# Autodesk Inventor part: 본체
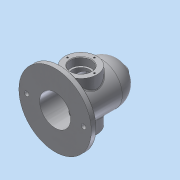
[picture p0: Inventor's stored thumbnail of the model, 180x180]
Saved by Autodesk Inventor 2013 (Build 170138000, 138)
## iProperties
Created: 2019-11
Part Number: 본체
Material: 알루미늄 6061
Document SubType Name: Modeling
Designer: Administrator
Density: 2.71 g/cm^3
Mass: 1114.82 g
Surface Area: 885.864 cm^2
Volume: 411.372 cm^3
Author: Administrator
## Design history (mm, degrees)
sketch "스케치1"
  geometry: C1 r 31 at (0, 0); 1 further point
  constraints: 1 centre point, 1 coincident
  dimensions: "d3" = 62 diameter of C1
extrude "돌출1" new body sketch "스케치1" stored distance "d4" = 100; taper "d5" = 0 deg
node "작업 평면1"
sketch "스케치2"
  geometry: C1 r 70 at (0, 0); 1 further point
  constraints: 1 centre point, 1 coincident
  dimensions: "d7" = 140 diameter of C1
extrude "돌출2" join sketch "스케치2" distance "d8" = 10; taper "d9" = 0 deg
sketch "스케치3"
  geometry: C1 r 70 at (0, 0) reference; C2 r 40 at (0, 0)
  constraints: 1 centre point, 1 coincident
  dimensions: "d10" = 80 diameter of C2
extrude "돌출3" join sketch "스케치3" distance "d11" = 80; taper "d12" = 0 deg
sketch "스케치5"
  geometry: L1 (31, -50)-(-31, -50) reference; L2 (-31, -50)-(-31, -40) reference; L3 (-40, 70)-(-40, 40) reference; L4 (-50, 70)-(-40, 70) reference; L5 (-50, -70)-(-50, 70) reference; L6 (-40, -70)-(-50, -70) reference; L7 (-40, -40)-(-40, -70) reference; L8 (-31, 40)-(-31, 50) reference; L9 (-31, 50)-(31, 50) reference; L10 (31, 50)-(31, 40) reference; L11 (31, 40)-(40, 40) reference; L12 (40, 40)-(40, -40) reference; L13 (40, -40)-(31, -40) reference; L14 (31, -40)-(31, -50) reference; L15 (-40, 40)-(-31, 40) reference; L16 (-31, -40)-(-40, -40) reference; A1 r 40 centre (40, 0) between (40, -40) and (40, 40); 1 further point
  constraints: 2 end point, 2 point on circle, 1 centre point, 1 midpoint
revolve "회전1" sketch "스케치5" stored, may be unused: angle "d13" = 90 deg
sketch "스케치6"
  geometry: C1 r 31 at (0, 0) reference; C2 r 20 at (0, 0)
  constraints: 1 centre point, 1 coincident
  dimensions: "d14" = 40 diameter of C2
extrude "돌출4" cut sketch "스케치6" distance "d15" = 15; taper "d16" = 0 deg
sketch "스케치7"
  geometry: C1 r 20 at (0, 0) reference; C2 r 16.5 at (0, 0)
  constraints: 1 centre point, 1 coincident
  dimensions: "d17" = 33 diameter of C2
extrude "돌출5" cut sketch "스케치7" stored distance "d18" = 15; taper "d19" = 0 deg
sketch "스케치8" dims "d20" = 52
  geometry: C1 r 20 at (0, 0) reference; C2 r 31 at (0, 0) reference; 2 further points
  constraints: 2 vertical alignment, 1 coincident, 2 other
hole "구멍1" sketch "스케치8" at (0, 26) diameter "d21" = 3.242; stored, may be unused: countersink angle "d25" = 90 deg, drill point angle "d27" = 118 deg; dims "d22" = 8, "d23" = 4, "d24" = 2, "d26" = 10
sketch "스케치9"
  geometry: L1 (40, -40)-(31, -40) reference; L2 (31, -40)-(31, -50) reference; L3 (31, -50)-(27.621, -50) reference; L4 (27.621, -50)-(27.621, -40) reference; L5 (27.621, -40)-(26, -39.026) reference; L6 (26, -39.026)-(24.379, -40) reference; L7 (24.379, -40)-(24.379, -50) reference; L8 (24.379, -50)-(20, -50) reference; L9 (20, -50)-(20, -35) reference; L10 (20, -35)-(16.5, -35) reference; L11 (16.5, -35)-(16.5, 35) reference; L12 (16.5, 35)-(20, 35) reference; L13 (20, 35)-(20, 50) reference; L14 (20, 50)-(24.379, 50) reference; L15 (24.379, 50)-(24.379, 40) reference; L16 (24.379, 40)-(26, 39.026) reference; L17 (26, 39.026)-(27.621, 40) reference; L18 (27.621, 40)-(27.621, 50) reference; L19 (27.621, 50)-(31, 50) reference; L20 (31, 50)-(31, 40) reference; L21 (31, 40)-(40, 40) reference; L22 (-50, 70)-(-40, 70) reference; L23 (-40, 70)-(-40, 40) reference; L24 (-40, 40)-(-31, 40) reference; L25 (-31, 40)-(-31, 50) reference; L26 (-31, 50)-(-27.621, 50) reference; L27 (-27.621, 50)-(-27.621, 40) reference; L28 (-27.621, 40)-(-26, 39.026) reference; L29 (-26, 39.026)-(-24.379, 40) reference; L30 (-24.379, 40)-(-24.379, 50) reference; L31 (-24.379, 50)-(-20, 50) reference; L32 (-20, 50)-(-20, 35) reference; L33 (-20, 35)-(-16.5, 35) reference; L34 (-16.5, 35)-(-16.5, -35) reference; L35 (-16.5, -35)-(-20, -35) reference; L36 (-20, -35)-(-20, -50) reference; L37 (-20, -50)-(-24.379, -50) reference; L38 (-24.379, -50)-(-24.379, -40) reference; L39 (-24.379, -40)-(-26, -39.026) reference; L40 (-26, -39.026)-(-27.621, -40) reference; L41 (-27.621, -40)-(-27.621, -50) reference; L42 (-27.621, -50)-(-31, -50) reference; L43 (-31, -50)-(-31, -40) reference; L44 (-31, -40)-(-40, -40) reference; L45 (-40, -40)-(-40, -70) reference; L46 (-40, -70)-(-50, -70) reference; L47 (-50, -70)-(-50, 70) reference; L48 (-50, 0)-(-50, 30); L49 (-50, 30)-(40, 30); L50 (40, 0.631)-(40, 0); L51 (40, -40)-(31, -40) reference; L52 (31, -40)-(31, -50) reference; L53 (31, -50)-(27.621, -50) reference; L54 (27.621, -50)-(27.621, -40) reference; L55 (27.621, -40)-(26, -39.026) reference; L56 (26, -39.026)-(24.379, -40) reference; L57 (24.379, -40)-(24.379, -50) reference; L58 (24.379, -50)-(20, -50) reference; L59 (20, -50)-(20, -35) reference; L60 (20, -35)-(16.5, -35) reference; L61 (16.5, -35)-(16.5, 35) reference; L62 (16.5, 35)-(20, 35) reference; L63 (20, 35)-(20, 50) reference; L64 (20, 50)-(24.379, 50) reference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; A1 r 40 centre (40, 0) between (80, 0) and (40, 40) reference; A2 r 40 centre (40, 0) between (40, -40) and (80, 0) reference; A3 r 30 centre (40, 0) between (70, 0) and (40, 30); A4 r 40 centre (40, 0) between (40, -40) and (80, 0) reference; A5 r 40 centre (40, 0) between (80, 0) and (40, 40) reference; 1 further point
  constraints: 8 end point, 3 perpendicular, 2 point on circle, 2 point on line, 1 centre point, 1 midpoint
  dimensions: "d32" = 90 distance of L48.start L50.end; "d35" = 30 distance of L50.end L98.end; "d36" = 30 radius of A3
revolve "회전2" sketch "스케치9" stored, may be unused: angle "d37" = 90 deg
node "작업 평면3"
  node "작업 평면2"
sketch "스케치11"
  geometry: C1 r 7.5 at (0, 0); 1 further point
  constraints: 1 centre point, 1 coincident
  dimensions: "d40" = 15 diameter of C1
extrude "돌출6" join sketch "스케치11" stored distance "d41" = 15; taper "d42" = 0 deg
sketch "스케치12"
  geometry: C1 r 7.5 at (0, 0) reference
hole "구멍2" sketch "스케치12" at (0, 0) diameter "d43" = 5.188; stored, may be unused: countersink angle "d47" = 90 deg, drill point angle "d49" = 118 deg; dims "d44" = 19, "d45" = 4, "d46" = 2, "d48" = 20
node "작업 평면6"
sketch "스케치17"
  geometry: L1 (-31, -50)-(31, -50) reference; L2 (50, -70)-(50, 70) reference; 2 further points
  constraints: 1 coincident, 1 other
feature "엠보싱1" sketch "스케치17" dims "d56" = 0.5, "d57" = 0
fillet "모깎기1" dims "d58" = 3
chamfer "모따기1" distance "d59" = 1; stored, may be unused: second distance "d60" = 2, angle "d61" = 45 deg
chamfer "모따기2" distance "d62" = 1; stored, may be unused: second distance "d63" = 2, angle "d64" = 45 deg
fillet "모깎기2" dims "d66" = 3
sketch "스케치19" dims "d71" = 110
  geometry: C1 r 69 at (0, 0) reference; C2 r 4.5 at (-55, 0); 1 further point
  constraints: 2 horizontal alignment, 1 centre point, 1 coincident, 2 other
  dimensions: "d72" = 9 diameter of C2
extrude "돌출8" cut sketch "스케치19" stored distance "d73" = 15; taper "d74" = 0 deg
node "솔리드1"
mirror "대칭1"
pattern_circular "원형 패턴1" dims angle "d30" = 360 deg
mirror "대칭2"
mirror "대칭3"
node "절단 모서리 투영2"
node "절단 모서리 투영3"
node "절단 모서리 투영4"
other parameters: "d39" = 5, "d53" = -83.25
